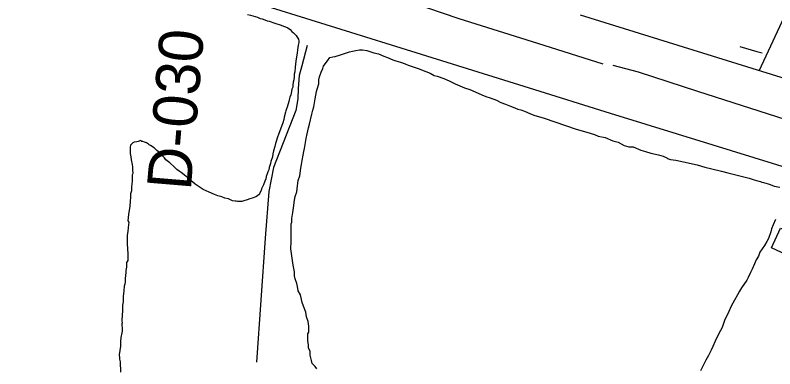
# Model space of a CAD drawing. Extents: x 3361039 to 3398939, y 576572 to 602007.
# Drawn here: x 3381254 to 3382684, y 583615 to 584281 of the extents above; entities that cross this region are included whole.
import ezdxf

# ---------------------------------------------------------------- set-up
doc = ezdxf.new("R2010")
doc.units = 0
for name, color, linetype in [('V-BLDG-OTLN', 7, 'Continuous'), ('V-RAIL-TRAK', 7, 'Continuous'), ('V-RIVR-RANG-IDEN', 7, 'Continuous'), ('V-ROAD-CNTR', 7, 'Continuous'), ('V-SITE-VEGE', 7, 'Continuous'), ('V-TOPO-SHOR', 7, 'Continuous')]:
    doc.layers.add(name, color=color, linetype=linetype)

msp = doc.modelspace()

# ---------------------------------------------------------------- linework, layer by layer
at = {"layer": 'V-BLDG-OTLN'}
msp.add_lwpolyline([(3382694.1, 583880.2), (3382731.5, 583865.6), (3382714.1, 583826.3), (3382677.7, 583843.3)], close=True, dxfattribs=at)
at = {"layer": 'V-RAIL-TRAK'}
msp.add_lwpolyline([(3384441, 583451.9), (3384235.3, 583516.2), (3384062.5, 583570.7), (3383909.9, 583618), (3383730.2, 583673.2), (3383554.2, 583728.4), (3383358, 583790.6), (3383176.4, 583848.4), (3383057.3, 583883.9), (3382930.2, 583923.7), (3382756.7, 583978.2), (3382567.5, 584036.6), (3382374.4, 584096.3), (3382221.9, 584143.7), (3382018.7, 584207.2), (3381857.3, 584257.2), (3381679.5, 584313), (3381485.2, 584372.7), (3381264.3, 584442.2), (3381071.9, 584501.2)], dxfattribs=at)
at = {"layer": 'V-ROAD-CNTR'}
for points in [[(3382654.2, 584176.7), (3383076.1, 585081.5)], [(3384263, 583676.6), (3382317.9, 584281.2)]]:
    msp.add_lwpolyline(points, dxfattribs=at)
at = {"layer": 'V-SITE-VEGE'}
for points in [[(3381690.9, 584282.6), (3381696.6, 584281.1), (3381709.5, 584277.4), (3381714.5, 584275.2), (3381718.8, 584274.5), (3381723.8, 584272.3), (3381728.1, 584270.8), (3381731.7, 584270.1), (3381742.4, 584266.4), (3381754.6, 584262.7), (3381758.9, 584260.6), (3381762.3, 584259.1), (3381766.8, 584257.6), (3381771.1, 584254), (3381774.6, 584250.4), (3381777.7, 584248.1), (3381782.5, 584243.2), (3381784.6, 584239.6), (3381786, 584238.1), (3381786.7, 584236), (3381787.4, 584232.4), (3381787.4, 584229.5), (3381786.6, 584224.5), (3381785.2, 584215.9), (3381784.4, 584209.4), (3381782.9, 584203), (3381782.1, 584194.4), (3381780.6, 584183.6), (3381779.8, 584174.3), (3381779.1, 584170), (3381779.1, 584164.9), (3381778.3, 584159.2), (3381776.8, 584154.9), (3381776.1, 584149.2), (3381776, 584145.6)], [(3381806, 583659.8), (3381804.6, 583668.4), (3381804.7, 583681.3), (3381806.2, 583684.2), (3381806.2, 583688.5), (3381806.3, 583695.7), (3381804.9, 583704.3), (3381802.1, 583712.9), (3381800.7, 583721.6), (3381796.5, 583733.1), (3381793.6, 583740.3), (3381790.9, 583754.7), (3381786.6, 583761.9), (3381785.2, 583770.5), (3381783.8, 583776.2), (3381781, 583784.9), (3381779.6, 583790.6), (3381779.7, 583797.8), (3381776.9, 583810.7), (3381774.2, 583828), (3381772.8, 583840.9), (3381772.9, 583855.3), (3381773.1, 583875.4), (3381773.1, 583878.2), (3381773.1, 583888.3), (3381774.6, 583891.2), (3381774.7, 583898.3), (3381776.2, 583909.8), (3381777.7, 583918.4), (3381779.2, 583932.7), (3381780.7, 583939.9), (3381783.6, 583948.5), (3381785.1, 583960), (3381786.6, 583970), (3381789.6, 583978.6), (3381791.1, 583993), (3381792.6, 584000.1), (3381794.1, 584007.3), (3381795.6, 584017.3), (3381797.1, 584024.5), (3381798.5, 584030.2), (3381800.1, 584041.7), (3381801.6, 584048.9), (3381803, 584057.5), (3381806, 584068.9), (3381807.5, 584076.1), (3381811.9, 584094.7), (3381813.9, 584102.3), (3381816.1, 584108.9), (3381817.4, 584116.2), (3381818.4, 584123.5), (3381820.8, 584137.7), (3381822.3, 584142), (3381825.2, 584152.1), (3381825.3, 584159.2), (3381826.8, 584165), (3381829.7, 584173.6), (3381832.6, 584180.7), (3381833.3, 584183.1), (3381834.1, 584185), (3381837, 584189.3), (3381841.3, 584195), (3381845.8, 584201.8), (3381851.6, 584203), (3381855.7, 584203.5), (3381865.8, 584206.3), (3381883.1, 584212), (3381888.8, 584213.3), (3381894.6, 584214.7), (3381901.8, 584216.1), (3381907.5, 584216.1), (3381915.9, 584214.7), (3381929, 584210.2), (3381937.6, 584208.7), (3381947.6, 584204.3), (3381954.8, 584201.4), (3381964.8, 584197), (3381970.5, 584195.5), (3381979.1, 584192.6), (3381988, 584189.3), (3381993.4, 584186.8), (3381999.2, 584185.3), (3382012.1, 584180.9), (3382026.4, 584175.1), (3382035, 584172.1), (3382042.1, 584167.8), (3382047.9, 584166.3), (3382060.7, 584161.9), (3382070.8, 584157.5), (3382082.2, 584151.7), (3382099.4, 584144.4), (3382109.4, 584141.5), (3382119.4, 584137.1), (3382132.3, 584131.2)], [(3381776, 584145.6), (3381774.6, 584142), (3381773.8, 584137.7), (3381772.4, 584131.3), (3381770.9, 584127), (3381769.4, 584121.9), (3381768.7, 584118.4), (3381765.7, 584108.3), (3381764.6, 584105.1), (3381763.3, 584101), (3381762.8, 584098.3), (3381759.9, 584089), (3381759.1, 584084.7), (3381757.6, 584078.2), (3381749.1, 584056.7), (3381747.4, 584051.8), (3381743.7, 584039.6), (3381742.2, 584033.9), (3381740, 584026), (3381738.6, 584020.2), (3381737.8, 584014.5), (3381734.9, 584005.9), (3381734.1, 584001.6), (3381731.9, 583994.4), (3381731.2, 583990.1), (3381729, 583985.9), (3381728.2, 583982.3), (3381726.1, 583977.3), (3381725.3, 583973), (3381723.8, 583968.7), (3381720.9, 583961.5), (3381718.7, 583956.5), (3381717.3, 583954.4), (3381716.5, 583950.8), (3381714.4, 583946.5), (3381713.6, 583944.3), (3381710, 583940.8), (3381706.4, 583939.4), (3381699.9, 583936.5), (3381695.6, 583935.1), (3381690.6, 583933.7), (3381684.1, 583931.6), (3381680.5, 583930.2), (3381671.9, 583930.3), (3381669.7, 583931), (3381667.6, 583931), (3381662.6, 583931.8), (3381655.4, 583935.4), (3381648.3, 583936.9), (3381642.5, 583939.1), (3381635.4, 583941.3), (3381628.9, 583943.5), (3381618.9, 583947.9), (3381607.5, 583953), (3381592.5, 583963.1), (3381587.5, 583967.5), (3381583.9, 583971.1), (3381579.6, 583974.7), (3381576, 583976.9), (3381571.8, 583980.5), (3381566, 583984.8), (3381562.5, 583987.7), (3381558.2, 583990.6), (3381553.2, 583995.7), (3381544.6, 584002.9), (3381537.5, 584008.7), (3381534.7, 584012.3), (3381529, 584018.1), (3381527.5, 584020.3), (3381525.4, 584022.5), (3381520.4, 584026.1), (3381515.4, 584031.1), (3381508.3, 584035.5), (3381506.1, 584036.9), (3381504.7, 584038.4), (3381501.1, 584040.6), (3381496.8, 584042), (3381494, 584043.5), (3381491.8, 584043.5), (3381490.4, 584045), (3381485.3, 584043.6), (3381482.5, 584042.9), (3381477.4, 584042.2), (3381475.3, 584040.8), (3381472.4, 584038.6), (3381470.9, 584036.5), (3381470.2, 584032.9), (3381470.1, 584020.7), (3381471.5, 584014.2), (3381472.2, 584008.5), (3381473.6, 583999.8), (3381474.2, 583994.8), (3381474.2, 583989.8), (3381474.9, 583983.3), (3381474.1, 583980.5), (3381474.1, 583968.3), (3381473.3, 583964), (3381472.5, 583956.8), (3381472.5, 583950.3), (3381471, 583944.6), (3381471, 583938.1)], [(3382132.3, 584131.2), (3382139.7, 584128.1), (3382148.1, 584125.4), (3382159.5, 584121), (3382168.1, 584116.6), (3382176.7, 584113.7), (3382186.1, 584109.8), (3382191, 584107.9), (3382195.8, 584105.8), (3382200.1, 584104.3), (3382205.5, 584102.9), (3382212.5, 584100.5), (3382222.5, 584096.2), (3382229.7, 584093.2), (3382249.7, 584087.4), (3382309.9, 584066.8), (3382329.9, 584061), (3382344.2, 584056.6), (3382351.4, 584053.6), (3382364.3, 584050.7), (3382378.6, 584044.8), (3382388.6, 584041.9), (3382400.1, 584036.1), (3382408.7, 584033.1), (3382417.3, 584033.1), (3382431.6, 584027.2), (3382440.2, 584024.3), (3382450.2, 584021.4), (3382464.6, 584018.4), (3382473.2, 584015.5), (3382480.3, 584012.5), (3382481.7, 584011.1), (3382487.5, 584009.6), (3382497.5, 584008.1), (3382511.8, 584005.1), (3382537.6, 583999.2), (3382552, 583994.8), (3382564.9, 583991.8), (3382583.5, 583987.4), (3382595, 583984.5), (3382605, 583981.5), (3382617.9, 583978.5), (3382627.9, 583976.1), (3382635.1, 583974.1), (3382645.1, 583971.2), (3382649.4, 583969.7), (3382653.4, 583968.4), (3382656.6, 583967.7), (3382659.4, 583966.8), (3382662.6, 583966), (3382670.9, 583963.8), (3382675.2, 583962.4), (3382682.4, 583959.4), (3382693.3, 583957.2)], [(3381471, 583938.1), (3381470.2, 583931.7), (3381469.4, 583920.9), (3381467.9, 583913.8), (3381467.2, 583905.9), (3381465.6, 583893.7), (3381467.8, 583891.5), (3381466.3, 583881.5), (3381465.5, 583873.6), (3381464.7, 583867.1), (3381464.6, 583849.9), (3381465.3, 583842), (3381465.9, 583831.2), (3381465.8, 583819), (3381462.9, 583815.5), (3381462.9, 583806.8), (3381462.1, 583800.4), (3381462.1, 583796.1), (3381461.3, 583791.8), (3381460.6, 583784.6), (3381460.5, 583778.9), (3381459.8, 583774.6), (3381459, 583771), (3381458.3, 583762.4), (3381457.5, 583756.6), (3381456.8, 583752.3), (3381456.7, 583741.6), (3381455.9, 583735.1), (3381455.8, 583722.2), (3381455.1, 583718.6), (3381455, 583714.3), (3381454.3, 583708.6), (3381454.3, 583705.7), (3381455, 583702.1), (3381454.2, 583700), (3381454.2, 583697.1), (3381454.9, 583692.8), (3381454.8, 583686.3), (3381454.1, 583682.7), (3381452.6, 583674.1), (3381451.8, 583666.2), (3381451.8, 583657.6), (3381449.5, 583641.8), (3381450.2, 583636.1), (3381450.2, 583633.6), (3381451.4, 583628.4), (3381451.9, 583609.1)], [(3382684.8, 583896.3), (3382680.4, 583886.2), (3382677.5, 583879.1), (3382676, 583873.3), (3382671.6, 583860.5), (3382668.7, 583854.7), (3382664.3, 583847.6), (3382655.6, 583834.7), (3382652.7, 583827.6), (3382648.4, 583820.4), (3382645.4, 583813.1), (3382641.1, 583803.2), (3382637.7, 583796.9), (3382633.8, 583787.5), (3382630.8, 583782.3), (3382620.7, 583767.5), (3382617.4, 583761.2), (3382613.4, 583754.6), (3382607.8, 583744.4), (3382601.8, 583733.2), (3382597.4, 583723.2), (3382588.7, 583706), (3382584.3, 583693.1), (3382578.5, 583681.7), (3382571.5, 583667), (3382566.8, 583657.3), (3382563.9, 583650.2), (3382558.9, 583640), (3382553.7, 583631.6), (3382543.5, 583611.6)], [(3381821.5, 583615.2), (3381818.6, 583619.5), (3381812.9, 583625.3), (3381811.5, 583631.1), (3381808.7, 583641.1), (3381808.8, 583648.3), (3381806, 583654.1), (3381806, 583659.8)]]:
    msp.add_lwpolyline(points, dxfattribs=at)
at = {"layer": 'V-TOPO-SHOR'}
for points in [[(3382360.6, 584188.9), (3382237.3, 584228.1), (3382089.6, 584274.6), (3381939.9, 584325.9), (3381866, 584343.1)], [(3381803.1, 584224.2), (3381793, 584185.9), (3381788, 584167.8), (3381786.5, 584143.3), (3381785.6, 584123.8), (3381782, 584101.5), (3381740, 583994.3), (3381731.3, 583949), (3381724.4, 583861.1), (3381708.1, 583628)], [(3382617.6, 584222.3), (3382649.6, 584213), (3382660.1, 584210.1)], [(3383064.8, 583968.2), (3382936, 584013.8), (3382720.7, 584078.9), (3382538.9, 584137.4), (3382426.8, 584173.8), (3382379.4, 584186.7)]]:
    msp.add_lwpolyline(points, dxfattribs=at)

# ---------------------------------------------------------------- texts
at = {"layer": 'V-RIVR-RANG-IDEN'}
msp.add_text('D-030', height=83, rotation=85.2081, dxfattribs=at).set_placement((3381584.1, 583949.9))

doc.saveas('drawing.dxf')
